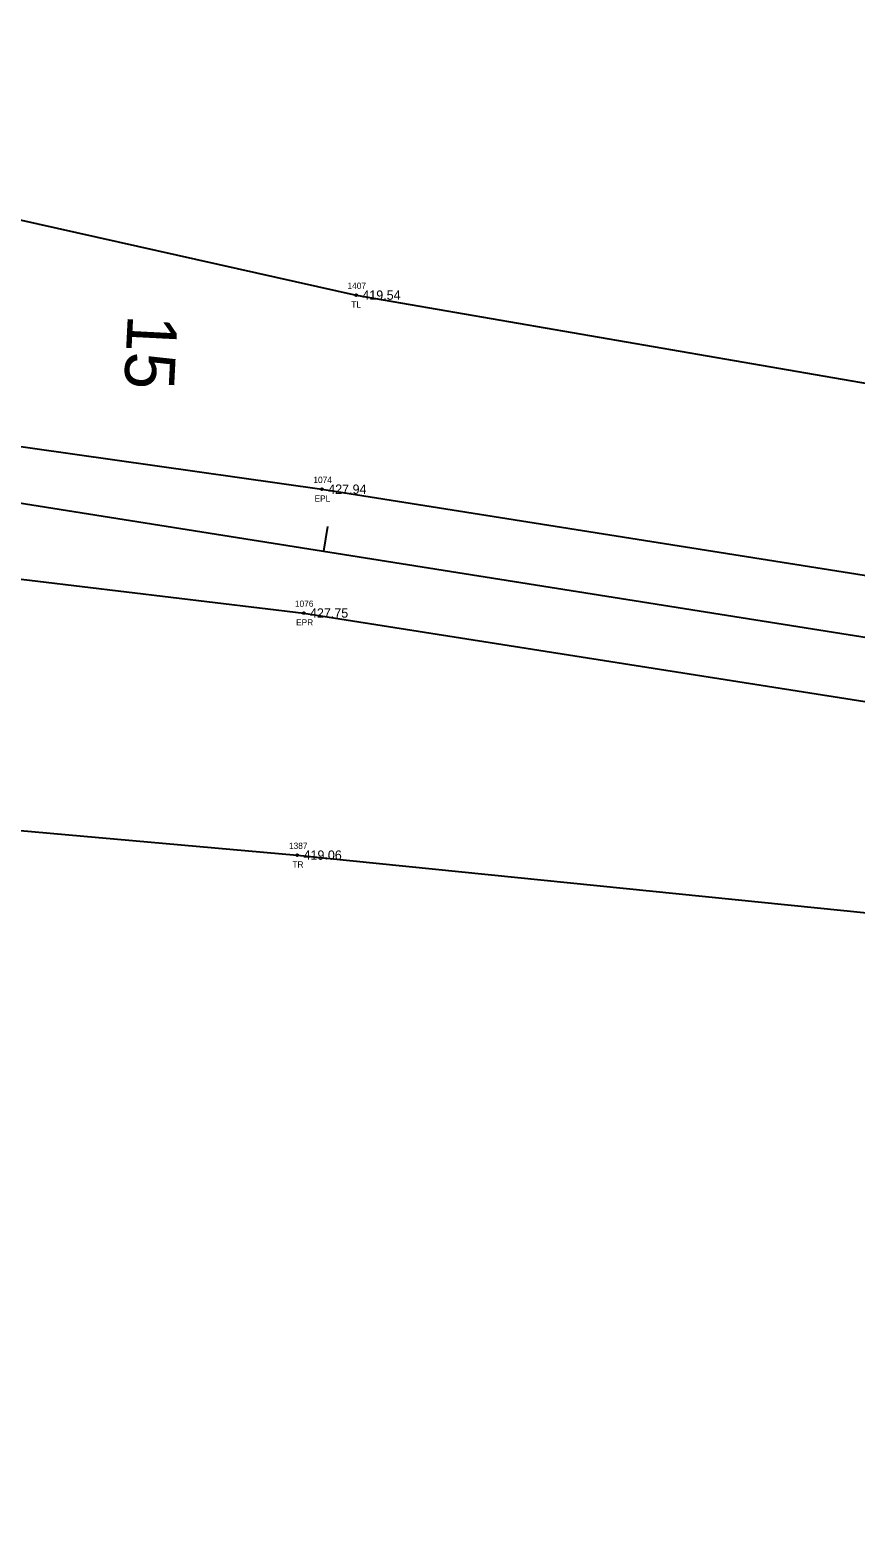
# Model space of a CAD drawing. Extents: x 1611114 to 1617038, y 769445 to 772083.
# Drawn here: x 1614019.1 to 1614151.5, y 771164.3 to 771406.3 of the extents above; entities that cross this region are included whole.
import ezdxf

# ---------------------------------------------------------------- set-up
doc = ezdxf.new("R2010")
doc.units = 0
for name, color, linetype in [('Default', 7, 'Continuous'), ('RD_EX_Road', 7, 'Continuous'), ('RD_EX_Road_txCode', 7, 'Continuous'), ('RD_EX_TX_Road_ELEV', 7, 'Continuous'), ('RD_EX_TX_VEG_ELEV', 7, 'Continuous'), ('RD_EX_VEG', 7, 'Continuous'), ('RD_EX_VEG_txCode', 7, 'Continuous'), ('RD_HC_Cl', 7, 'Continuous'), ('RD_HC_Data_Tic', 7, 'Continuous'), ('RD_HC_TX_Sta50', 7, 'Continuous'), ('RD_SMD_Locator', 7, 'Continuous')]:
    doc.layers.add(name, color=color, linetype=linetype)

msp = doc.modelspace()

# ---------------------------------------------------------------- linework, layer by layer
at = {"layer": 'Default'}
msp.add_line((1614000.69, 771333.06), (1615062.36, 771164.28), dxfattribs=at)
at = {"layer": 'RD_EX_Road'}
for points in [[(1613966.21, 771346.72), (1614065.91, 771332.61), (1614166, 771316.74), (1614252.8, 771303.53), (1614264.27, 771301.76), (1614271.95, 771300.8), (1614363.43, 771285.99), (1614463.49, 771269.68), (1614562.24, 771253.72), (1614661.91, 771238.32)], [(1613963.41, 771324.71), (1614062.98, 771312.73), (1614162.48, 771297.04), (1614260.87, 771281.9), (1614360.23, 771265.95), (1614460.24, 771249.77), (1614559.17, 771233.87), (1614658.84, 771218.34)]]:
    msp.add_lwpolyline(points, dxfattribs=at)
at = {"layer": 'RD_EX_VEG'}
for points in [[(1613190.16, 771350.86), (1613289.21, 771359.12), (1613387.94, 771369.51), (1613489.82, 771379.95), (1613503.78, 771396.75), (1613539.01, 771398.99), (1613588.71, 771402.91), (1613642.02, 771405.83), (1613690.35, 771406.29), (1613743.43, 771406.09), (1613794.76, 771402.87), (1613849.1, 771400.75), (1613898.57, 771402.5), (1614071.38, 771363.76), (1614171, 771346.54), (1614270.56, 771328.42), (1614365.98, 771308.81), (1614467.36, 771290.78), (1614565.75, 771274.12), (1614666.78, 771259.85)], [(1613196.47, 771290.95), (1613297.34, 771299.06), (1613395.35, 771312.89), (1613495.9, 771312.14), (1613544.51, 771308.67), (1613596.05, 771312.86), (1613644.8, 771313.72), (1613693.08, 771315.9), (1613741.59, 771313.35), (1613789.13, 771312.23), (1613836.26, 771305.8), (1613884.78, 771289.64), (1614061.95, 771273.87), (1614158.04, 771264.13), (1614253.51, 771253.52), (1614356.63, 771247.59), (1614457.77, 771232.22), (1614557.61, 771219.54), (1614658.3, 771205.52)]]:
    msp.add_lwpolyline(points, dxfattribs=at)
at = {"layer": 'RD_HC_Cl'}
msp.add_line((1614000.69, 771333.06), (1615062.36, 771164.28), dxfattribs=at)
at = {"layer": 'RD_HC_Data_Tic'}
msp.add_line((1614066.2, 771322.65), (1614066.83, 771326.6), dxfattribs=at)
at = {"layer": 'RD_SMD_Locator'}
for centre in [(1614071.38, 771363.76), (1614065.91, 771332.61), (1614062.98, 771312.73), (1614061.95, 771273.87)]:
    msp.add_circle(centre, 0.15, dxfattribs=at)

# ---------------------------------------------------------------- texts
at = {"layer": 'RD_EX_Road_txCode'}
for s, p in [('1074', (1614064.53, 771333.61)), ('EPL', (1614064.71, 771330.61)), ('1076', (1614061.57, 771313.73)), ('EPR', (1614061.75, 771310.73))]:
    msp.add_text(s, height=1, dxfattribs=at).set_placement(p)
at = {"layer": 'RD_EX_TX_Road_ELEV'}
for s, p in [('427.94', (1614066.91, 771331.86)), ('427.75', (1614063.98, 771311.98))]:
    msp.add_text(s, height=1.5, dxfattribs=at).set_placement(p)
at = {"layer": 'RD_EX_TX_VEG_ELEV'}
for s, p in [('419.54', (1614072.38, 771363.01)), ('419.06', (1614062.95, 771273.12))]:
    msp.add_text(s, height=1.5, dxfattribs=at).set_placement(p)
at = {"layer": 'RD_EX_VEG_txCode'}
for s, p in [('1407', (1614070, 771364.76)), ('TL', (1614070.61, 771361.76)), ('1387', (1614060.61, 771274.87)), ('TR', (1614061.16, 771271.87))]:
    msp.add_text(s, height=1, dxfattribs=at).set_placement(p)
at = {"layer": 'RD_HC_TX_Sta50'}
msp.add_text('15', height=8, rotation=267.08, dxfattribs=at).set_placement((1614034.78, 771360.72))

doc.saveas('drawing.dxf')
